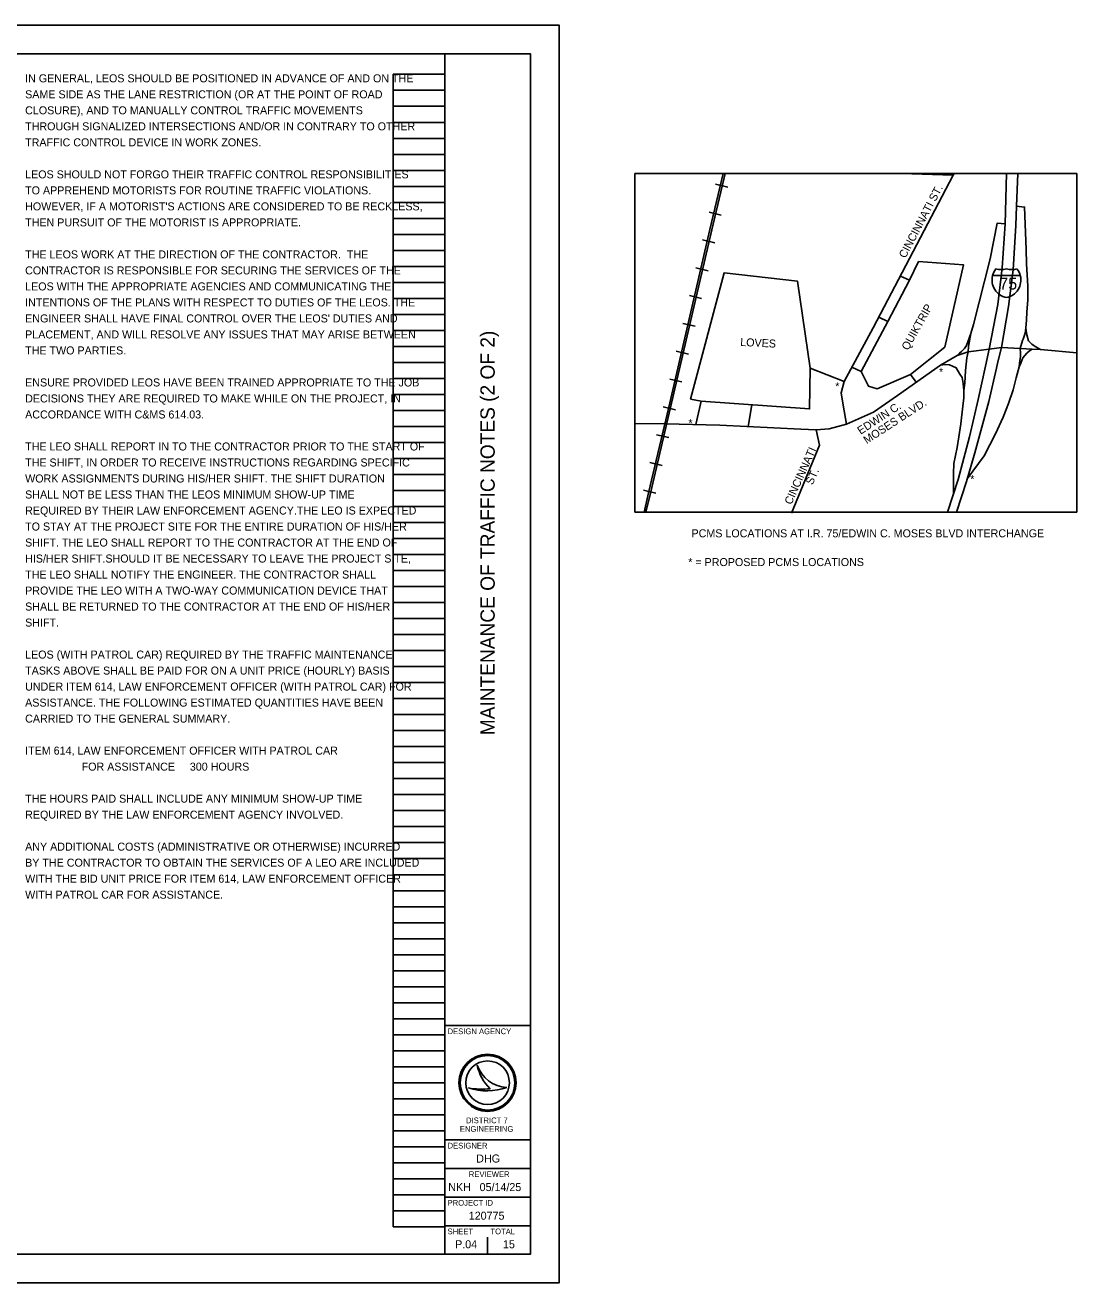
# Model space of a CAD drawing. Extents: x 0 to 43.1, y 0 to 22.
# Drawn here: x 24.66 to 43.06, y 0 to 22 of the extents above; entities that cross this region are included whole.
import ezdxf

# ---------------------------------------------------------------- set-up
doc = ezdxf.new("R2010")
doc.units = 0
for name, color, linetype in [('Default', 7, 'Continuous'), ('GM_X_City_Street', 7, 'Continuous'), ('GM_X_Interchange_Ramps', 7, 'Continuous'), ('GM_X_Interstate_Route', 7, 'Continuous'), ('GM_X_Interstate_Shield', 7, 'Continuous'), ('GM_X_Rail_Line', 7, 'Continuous'), ('SC_Scratch1', 7, 'Continuous'), ('SH_Border', 7, 'Continuous'), ('SH_Cut_Line', 7, 'Continuous'), ('SH_Data', 7, 'Continuous'), ('SH_Text', 7, 'Continuous')]:
    doc.layers.add(name, color=color, linetype=linetype)

msp = doc.modelspace()

# ---------------------------------------------------------------- linework, layer by layer
at = {"layer": 'Default'}
for p, q in [((43.059, 19.405), (35.326, 19.405)), ((35.326, 13.479), (35.326, 19.405)), ((43.059, 13.479), (43.059, 19.405)), ((43.059, 13.479), (35.326, 13.479))]:
    msp.add_line(p, q, dxfattribs=at)
at = {"layer": 'GM_X_City_Street'}
for p, q in [((39.991, 19.405), (40.898, 19.374)), ((38.987, 15.766), (38.396, 15.997)), ((36.393, 15.012), (36.489, 15.42)), ((37.373, 15.358), (37.31, 14.977))]:
    msp.add_line(p, q, dxfattribs=at)
for points in [[(39.032, 15.023), (38.971, 15.354), (38.938, 15.568), (38.987, 15.766), (39.498, 16.705), (40.898, 19.374), (40.915, 19.405)], [(40.672, 16.052), (40.965, 16.222), (41.157, 16.283), (41.527, 16.332)], [(41.527, 16.332), (41.74, 16.361), (42.069, 16.344), (42.278, 16.333), (42.421, 16.325), (43.059, 16.266)], [(39.032, 15.023), (39.504, 15.232), (39.921, 15.52), (40.672, 16.052)], [(35.326, 15.033), (35.861, 15.025), (36.814, 15.001), (38.233, 14.933), (38.367, 14.928)], [(38.367, 14.928), (38.5, 14.922), (38.729, 14.94), (39.032, 15.023)], [(38.5, 14.922), (38.555, 14.652), (38.068, 13.466)]]:
    msp.add_lwpolyline(points, dxfattribs=at)
at = {"layer": 'GM_X_Interchange_Ramps'}
for points in [[(42.172, 18.073), (42.146, 18.818), (42.006, 18.831)], [(41.804, 18.527), (41.666, 18.538), (41.54, 17.915), (41.252, 16.761)], [(42.176, 16.844), (42.185, 16.981), (42.203, 17.193), (42.199, 17.432), (42.181, 17.825), (42.172, 18.073)], [(41.252, 16.761), (41.206, 16.606), (41.13, 16.395), (41.093, 16.343), (41.042, 16.291), (41.009, 16.264), (40.965, 16.222)], [(41.252, 16.761), (41.206, 16.606), (41.166, 16.38), (41.157, 16.283)], [(42.069, 16.344), (42.106, 16.482), (42.119, 16.507), (42.154, 16.611), (42.165, 16.699), (42.176, 16.844)], [(42.421, 16.325), (42.331, 16.376), (42.27, 16.422), (42.212, 16.478), (42.184, 16.581), (42.165, 16.699), (42.176, 16.844)], [(41.157, 16.283), (41.134, 16.183), (41.11, 15.957), (41.101, 15.737), (41.08, 15.609)], [(41.142, 14.063), (41.44, 14.466), (41.634, 14.85), (41.769, 15.143), (41.864, 15.383), (41.945, 15.622), (41.995, 15.829), (42.048, 16.026), (42.079, 16.09), (42.117, 16.178), (42.148, 16.224), (42.185, 16.265), (42.228, 16.302), (42.278, 16.333)], [(42.048, 16.026), (42.064, 16.135), (42.072, 16.198), (42.076, 16.26), (42.069, 16.344)], [(40.672, 16.052), (40.762, 16.066), (40.832, 16.056), (40.883, 16.036), (40.948, 16.007), (41.013, 15.894), (41.05, 15.835), (41.069, 15.732), (41.08, 15.609), (41.08, 15.48), (41.065, 15.336), (41.029, 15.024), (40.995, 14.801), (40.965, 14.614), (40.909, 14.335), (40.9, 14.159), (40.904, 13.81)]]:
    msp.add_lwpolyline(points, dxfattribs=at)
at = {"layer": 'GM_X_Interstate_Route'}
for p, q in [((42.006, 18.831), (42.028, 19.405)), ((40.797, 13.479), (40.984, 14.055))]:
    msp.add_line(p, q, dxfattribs=at)
for points in [[(40.984, 14.055), (41.18, 14.796), (41.33, 15.451), (41.462, 16.034), (41.527, 16.332), (41.676, 17.113), (41.755, 17.756), (41.804, 18.527), (41.831, 19.405)], [(41.678, 16.108), (41.74, 16.361), (41.866, 17.079), (41.945, 17.722), (41.994, 18.493), (42.006, 18.831)], [(41.273, 14.52), (41.52, 15.417), (41.652, 16), (41.678, 16.108)], [(40.954, 13.479), (41.129, 14.018), (41.273, 14.52)]]:
    msp.add_lwpolyline(points, dxfattribs=at)
at = {"layer": 'GM_X_Interstate_Shield'}
for p, q in [((41.586, 17.619), (42.07, 17.619)), ((42.07, 17.619), (41.586, 17.619)), ((42.07, 17.619), (41.586, 17.619))]:
    msp.add_line(p, q, dxfattribs=at)
for centre, start, end in [((41.891, 17.542), 165.8066, 258.463), ((41.891, 17.542), 141.669, 165.8066), ((41.736, 18.038), 253.0091, 286.9909), ((41.92, 18.038), 253.0091, 286.9909), ((41.765, 17.542), 281.537, 14.1934), ((41.765, 17.542), 14.1934, 38.331)]:
    msp.add_arc(centre, 0.315, start, end, dxfattribs=at)
at = {"layer": 'GM_X_Rail_Line'}
for p, q in [((36.739, 19.216), (36.954, 19.165)), ((36.624, 18.729), (36.839, 18.678)), ((36.509, 18.242), (36.725, 18.192)), ((36.395, 17.756), (36.61, 17.705)), ((36.28, 17.269), (36.495, 17.218)), ((36.165, 16.782), (36.38, 16.732)), ((36.05, 16.296), (36.266, 16.245)), ((35.936, 15.809), (36.151, 15.758)), ((35.821, 15.322), (36.036, 15.272)), ((35.706, 14.836), (35.921, 14.785)), ((35.591, 14.349), (35.807, 14.298)), ((35.477, 13.863), (35.692, 13.812))]:
    msp.add_line(p, q, dxfattribs=at)
for points in [[(35.487, 13.479), (35.566, 13.82), (35.92, 15.316), (36.64, 18.424), (36.872, 19.405)], [(35.52, 13.479), (35.598, 13.812), (35.952, 15.309), (36.672, 18.417), (36.905, 19.405)]]:
    msp.add_lwpolyline(points, dxfattribs=at)
at = {"layer": 'SC_Scratch1'}
for p, q in [((31.1, 0.98), (31.1, 21.14)), ((31.1, 21.14), (32, 21.14)), ((32, 0.98), (32, 21.14)), ((31.1, 20.86), (32, 20.86)), ((31.1, 20.58), (32, 20.58)), ((31.1, 20.3), (32, 20.3)), ((31.1, 20.02), (32, 20.02)), ((31.1, 19.74), (32, 19.74)), ((31.1, 19.46), (32, 19.46)), ((31.1, 19.18), (32, 19.18)), ((31.1, 18.9), (32, 18.9)), ((31.1, 18.62), (32, 18.62)), ((31.1, 18.34), (32, 18.34)), ((31.1, 18.06), (32, 18.06)), ((31.1, 17.78), (32, 17.78)), ((31.1, 17.5), (32, 17.5)), ((31.1, 17.22), (32, 17.22)), ((31.1, 16.94), (32, 16.94)), ((31.1, 16.66), (32, 16.66)), ((31.1, 16.38), (32, 16.38)), ((31.1, 16.1), (32, 16.1)), ((31.1, 15.82), (32, 15.82)), ((31.1, 15.54), (32, 15.54)), ((31.1, 15.26), (32, 15.26)), ((31.1, 14.98), (32, 14.98)), ((31.1, 14.7), (32, 14.7)), ((31.1, 14.42), (32, 14.42)), ((31.1, 14.14), (32, 14.14)), ((31.1, 13.86), (32, 13.86)), ((31.1, 13.58), (32, 13.58)), ((31.1, 13.3), (32, 13.3)), ((31.1, 13.02), (32, 13.02)), ((31.1, 12.74), (32, 12.74)), ((31.1, 12.46), (32, 12.46)), ((31.1, 12.18), (32, 12.18)), ((31.1, 11.9), (32, 11.9)), ((31.1, 11.62), (32, 11.62)), ((31.1, 11.34), (32, 11.34)), ((31.1, 11.06), (32, 11.06)), ((31.1, 10.78), (32, 10.78)), ((31.1, 10.5), (32, 10.5)), ((31.1, 10.22), (32, 10.22)), ((31.1, 9.94), (32, 9.94)), ((31.1, 9.66), (32, 9.66)), ((31.1, 9.38), (32, 9.38)), ((31.1, 9.1), (32, 9.1)), ((31.1, 8.82), (32, 8.82)), ((31.1, 8.54), (32, 8.54)), ((31.1, 8.26), (32, 8.26)), ((31.1, 7.98), (32, 7.98)), ((31.1, 7.7), (32, 7.7)), ((31.1, 7.42), (32, 7.42)), ((31.1, 7.14), (32, 7.14)), ((31.1, 6.86), (32, 6.86)), ((31.1, 6.58), (32, 6.58)), ((31.1, 6.3), (32, 6.3)), ((31.1, 6.02), (32, 6.02)), ((31.1, 5.74), (32, 5.74)), ((31.1, 5.46), (32, 5.46)), ((31.1, 5.18), (32, 5.18)), ((31.1, 4.9), (32, 4.9)), ((31.1, 4.62), (32, 4.62)), ((31.1, 4.34), (32, 4.34)), ((31.1, 4.06), (32, 4.06)), ((31.1, 3.78), (32, 3.78)), ((31.1, 3.5), (32, 3.5)), ((31.1, 3.22), (32, 3.22)), ((31.1, 2.94), (32, 2.94)), ((31.1, 2.66), (32, 2.66)), ((31.1, 2.38), (32, 2.38)), ((31.1, 2.1), (32, 2.1)), ((31.1, 1.82), (32, 1.82)), ((31.1, 1.54), (32, 1.54)), ((31.1, 1.26), (32, 1.26)), ((31.1, 0.98), (32, 0.98))]:
    msp.add_line(p, q, dxfattribs=at)
at = {"layer": 'SH_Border'}
for p, q in [((32, 0.5), (32, 21.5)), ((32, 4.5), (33.5, 4.5)), ((32, 2.5), (33.5, 2.5)), ((32, 2), (33.5, 2)), ((32, 1.5), (33.5, 1.5)), ((32, 1), (33.5, 1))]:
    msp.add_line(p, q, dxfattribs=at)
msp.add_lwpolyline([(1.5, 21.5), (33.5, 21.5), (33.5, 0.5), (1.5, 0.5)], close=True, dxfattribs=at)
at = {"layer": 'SH_Cut_Line'}
msp.add_lwpolyline([(0, 0), (34, 0), (34, 22), (0, 22)], close=True, dxfattribs=at)
at = {"layer": 'SH_Data'}
for p, q in [((32.567, 3.81), (32.567, 3.81)), ((32.417, 3.41), (32.417, 3.41)), ((32.75, 3.5), (32.75, 3.5)), ((33.087, 3.419), (33.087, 3.419)), ((32.375, 0.675), (32.375, 0.675)), ((32.75, 0.5), (32.75, 0.8))]:
    msp.add_line(p, q, dxfattribs=at)
for radius in [0.5, 0.477, 0.477, 0.382]:
    msp.add_circle((32.75, 3.5), radius, dxfattribs=at)
for centre, radius, start, end in [((33.116, 3.998), 0.58, 198.9257, 198.9319), ((33.347, 3.97), 0.796, 191.6379, 191.6421), ((33.116, 3.998), 0.58, 198.9319, 267.1657), ((33.347, 3.97), 0.796, 191.6421, 226.0947), ((32.739, 4.37), 1.013, 251.4576, 290.0832), ((32.648, 4.654), 1.266, 259.4964, 259.4995), ((32.739, 4.37), 1.013, 251.4527, 251.4576), ((32.648, 4.654), 1.266, 259.4995, 276.6672)]:
    msp.add_arc(centre, radius, start, end, dxfattribs=at)
at = {"layer": 'SH_Text'}
for p, q in [((39.974, 17.612), (40.129, 17.537)), ((39.596, 16.892), (39.751, 16.818)), ((39.124, 16.018), (39.285, 15.939)), ((40.25, 15.753), (40.148, 15.892))]:
    msp.add_line(p, q, dxfattribs=at)
for points in [[(39.285, 15.939), (39.414, 15.685), (39.567, 15.639), (40.148, 15.892), (40.749, 16.369), (41.076, 17.808), (40.291, 17.864), (40.129, 17.537), (39.751, 16.818)], [(36.303, 15.456), (36.89, 17.668), (38.175, 17.519), (38.396, 15.997), (38.384, 15.287), (36.489, 15.42)]]:
    msp.add_lwpolyline(points, close=True, dxfattribs=at)

# ---------------------------------------------------------------- texts
at = {"layer": 'GM_X_Interstate_Shield'}
msp.add_text('75', height=0.2097, dxfattribs=at).set_placement((41.703, 17.375))
at = {"layer": 'SH_Data'}
msp.add_text('MAINTENANCE OF TRAFFIC NOTES (2 OF 2)', height=0.25, rotation=90, dxfattribs=at).set_placement((32.875, 9.579))
for s, height, p in [('DESIGN AGENCY', 0.1, (32.05, 4.35)), ('DESIGNER', 0.1, (32.05, 2.35)), ('DHG', 0.14, (32.552, 2.105)), ('REVIEWER', 0.1, (32.422, 1.85)), ('NKH', 0.14, (32.062, 1.605)), ('05/14/25', 0.14, (32.611, 1.605)), ('PROJECT ID', 0.1, (32.05, 1.35)), ('120775', 0.14, (32.421, 1.105)), ('SHEET', 0.1, (32.05, 0.85)), ('TOTAL', 0.1, (32.8, 0.85)), ('P.04', 0.14, (32.182, 0.605)), ('15', 0.14, (33.02, 0.605))]:
    msp.add_text(s, height=height, dxfattribs=at).set_placement(p)
at = {"layer": 'SH_Text'}
for s, height, p in [('IN GENERAL, LEOS SHOULD BE POSITIONED IN ADVANCE OF AND ON THE ', 0.14, (24.66, 21)), ('SAME SIDE AS THE LANE RESTRICTION (OR AT THE POINT OF ROAD ', 0.14, (24.66, 20.72)), ('CLOSURE), AND TO MANUALLY CONTROL TRAFFIC MOVEMENTS ', 0.14, (24.66, 20.44)), ('THROUGH SIGNALIZED INTERSECTIONS AND/OR IN CONTRARY TO OTHER ', 0.14, (24.66, 20.16)), ('TRAFFIC CONTROL DEVICE IN WORK ZONES.', 0.14, (24.66, 19.88)), ('LEOS SHOULD NOT FORGO THEIR TRAFFIC CONTROL RESPONSIBILITIES ', 0.14, (24.66, 19.32)), ('TO APPREHEND MOTORISTS FOR ROUTINE TRAFFIC VIOLATIONS. ', 0.14, (24.66, 19.04)), ("HOWEVER, IF A MOTORIST'S ACTIONS ARE CONSIDERED TO BE RECKLESS, ", 0.14, (24.66, 18.76)), ('THEN PURSUIT OF THE MOTORIST IS APPROPRIATE.', 0.14, (24.66, 18.48)), ('THE LEOS WORK AT THE DIRECTION OF THE CONTRACTOR.  THE ', 0.14, (24.66, 17.92)), ('CONTRACTOR IS RESPONSIBLE FOR SECURING THE SERVICES OF THE ', 0.14, (24.66, 17.64)), ('LEOS WITH THE APPROPRIATE AGENCIES AND COMMUNICATING THE ', 0.14, (24.66, 17.36)), ('INTENTIONS OF THE PLANS WITH RESPECT TO DUTIES OF THE LEOS. THE ', 0.14, (24.66, 17.08)), ("ENGINEER SHALL HAVE FINAL CONTROL OVER THE LEOS' DUTIES AND ", 0.14, (24.66, 16.8)), ('PLACEMENT, AND WILL RESOLVE ANY ISSUES THAT MAY ARISE BETWEEN ', 0.14, (24.66, 16.52)), ('THE TWO PARTIES.', 0.14, (24.66, 16.24)), ('*', 0.14, (40.647, 15.866)), ('ENSURE PROVIDED LEOS HAVE BEEN TRAINED APPROPRIATE TO THE JOB ', 0.14, (24.66, 15.68)), ('*', 0.14, (38.833, 15.613)), ('DECISIONS THEY ARE REQUIRED TO MAKE WHILE ON THE PROJECT, IN ', 0.14, (24.66, 15.4)), ('ACCORDANCE WITH C&MS 614.03.', 0.14, (24.66, 15.12)), ('*', 0.14, (36.265, 14.969)), ('THE LEO SHALL REPORT IN TO THE CONTRACTOR PRIOR TO THE START OF ', 0.14, (24.66, 14.56)), ('THE SHIFT, IN ORDER TO RECEIVE INSTRUCTIONS REGARDING SPECIFIC ', 0.14, (24.66, 14.28)), ('WORK ASSIGNMENTS DURING HIS/HER SHIFT. THE SHIFT DURATION ', 0.14, (24.66, 14)), ('*', 0.14, (41.195, 13.99)), ('SHALL NOT BE LESS THAN THE LEOS MINIMUM SHOW-UP TIME ', 0.14, (24.66, 13.72)), ('REQUIRED BY THEIR LAW ENFORCEMENT AGENCY.THE LEO IS EXPECTED ', 0.14, (24.66, 13.44)), ('TO STAY AT THE PROJECT SITE FOR THE ENTIRE DURATION OF HIS/HER ', 0.14, (24.66, 13.16)), ('SHIFT. THE LEO SHALL REPORT TO THE CONTRACTOR AT THE END OF ', 0.14, (24.66, 12.88)), ('PCMS LOCATIONS AT I.R. 75/EDWIN C. MOSES BLVD INTERCHANGE', 0.14, (36.318, 13.041)), ('HIS/HER SHIFT.SHOULD IT BE NECESSARY TO LEAVE THE PROJECT SITE, ', 0.14, (24.66, 12.6)), ('* = PROPOSED PCMS LOCATIONS', 0.14, (36.261, 12.538)), ('THE LEO SHALL NOTIFY THE ENGINEER. THE CONTRACTOR SHALL ', 0.14, (24.66, 12.32)), ('PROVIDE THE LEO WITH A TWO-WAY COMMUNICATION DEVICE THAT ', 0.14, (24.66, 12.04)), ('SHALL BE RETURNED TO THE CONTRACTOR AT THE END OF HIS/HER ', 0.14, (24.66, 11.76)), ('SHIFT.', 0.14, (24.66, 11.48)), ('LEOS (WITH PATROL CAR) REQUIRED BY THE TRAFFIC MAINTENANCE ', 0.14, (24.66, 10.92)), ('TASKS ABOVE SHALL BE PAID FOR ON A UNIT PRICE (HOURLY) BASIS ', 0.14, (24.66, 10.64)), ('UNDER ITEM 614, LAW ENFORCEMENT OFFICER (WITH PATROL CAR) FOR ', 0.14, (24.66, 10.36)), ('ASSISTANCE. THE FOLLOWING ESTIMATED QUANTITIES HAVE BEEN ', 0.14, (24.66, 10.08)), ('CARRIED TO THE GENERAL SUMMARY.', 0.14, (24.66, 9.8)), ('ITEM 614, LAW ENFORCEMENT OFFICER WITH PATROL CAR', 0.14, (24.66, 9.24)), ('                   FOR ASSISTANCE     300 HOURS', 0.14, (24.66, 8.96)), ('THE HOURS PAID SHALL INCLUDE ANY MINIMUM SHOW-UP TIME ', 0.14, (24.66, 8.4)), ('REQUIRED BY THE LAW ENFORCEMENT AGENCY INVOLVED.', 0.14, (24.66, 8.12)), ('ANY ADDITIONAL COSTS (ADMINISTRATIVE OR OTHERWISE) INCURRED ', 0.14, (24.66, 7.56)), ('BY THE CONTRACTOR TO OBTAIN THE SERVICES OF A LEO ARE INCLUDED ', 0.14, (24.66, 7.28)), ('WITH THE BID UNIT PRICE FOR ITEM 614, LAW ENFORCEMENT OFFICER ', 0.14, (24.66, 7)), ('WITH PATROL CAR FOR ASSISTANCE.', 0.14, (24.66, 6.72)), ('DISTRICT 7', 0.1, (32.374, 2.792)), ('ENGINEERING', 0.1, (32.265, 2.642))]:
    msp.add_text(s, height=height, dxfattribs=at).set_placement(p)
for s, rotation, p in [('CINCINNATI ST.', 62.1388, (40.06, 17.912)), ('QUIKTRIP', 60.6004, (40.105, 16.301)), ('LOVES', 357.1943, (37.168, 16.389)), ('MOSES BLVD.', 33.0982, (39.383, 14.669)), ('EDWIN C.', 33.0982, (39.276, 14.833)), ('CINCINNATI', 65.7883, (38.064, 13.601)), ('         ST.', 65.7883, (38.243, 13.52))]:
    msp.add_text(s, height=0.14, rotation=rotation, dxfattribs=at).set_placement(p)

doc.saveas('drawing.dxf')
